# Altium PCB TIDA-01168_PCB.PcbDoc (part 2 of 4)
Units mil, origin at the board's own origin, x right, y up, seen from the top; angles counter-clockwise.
Board outline 7874.02 x 8344.02 mil, 4 copper layers (Top Layer, Signal Layer 1, Signal Layer 2, Bottom Layer), stack 65.748 mil thick; 480 components, 223 nets, 1266 pads, 1791 vias.
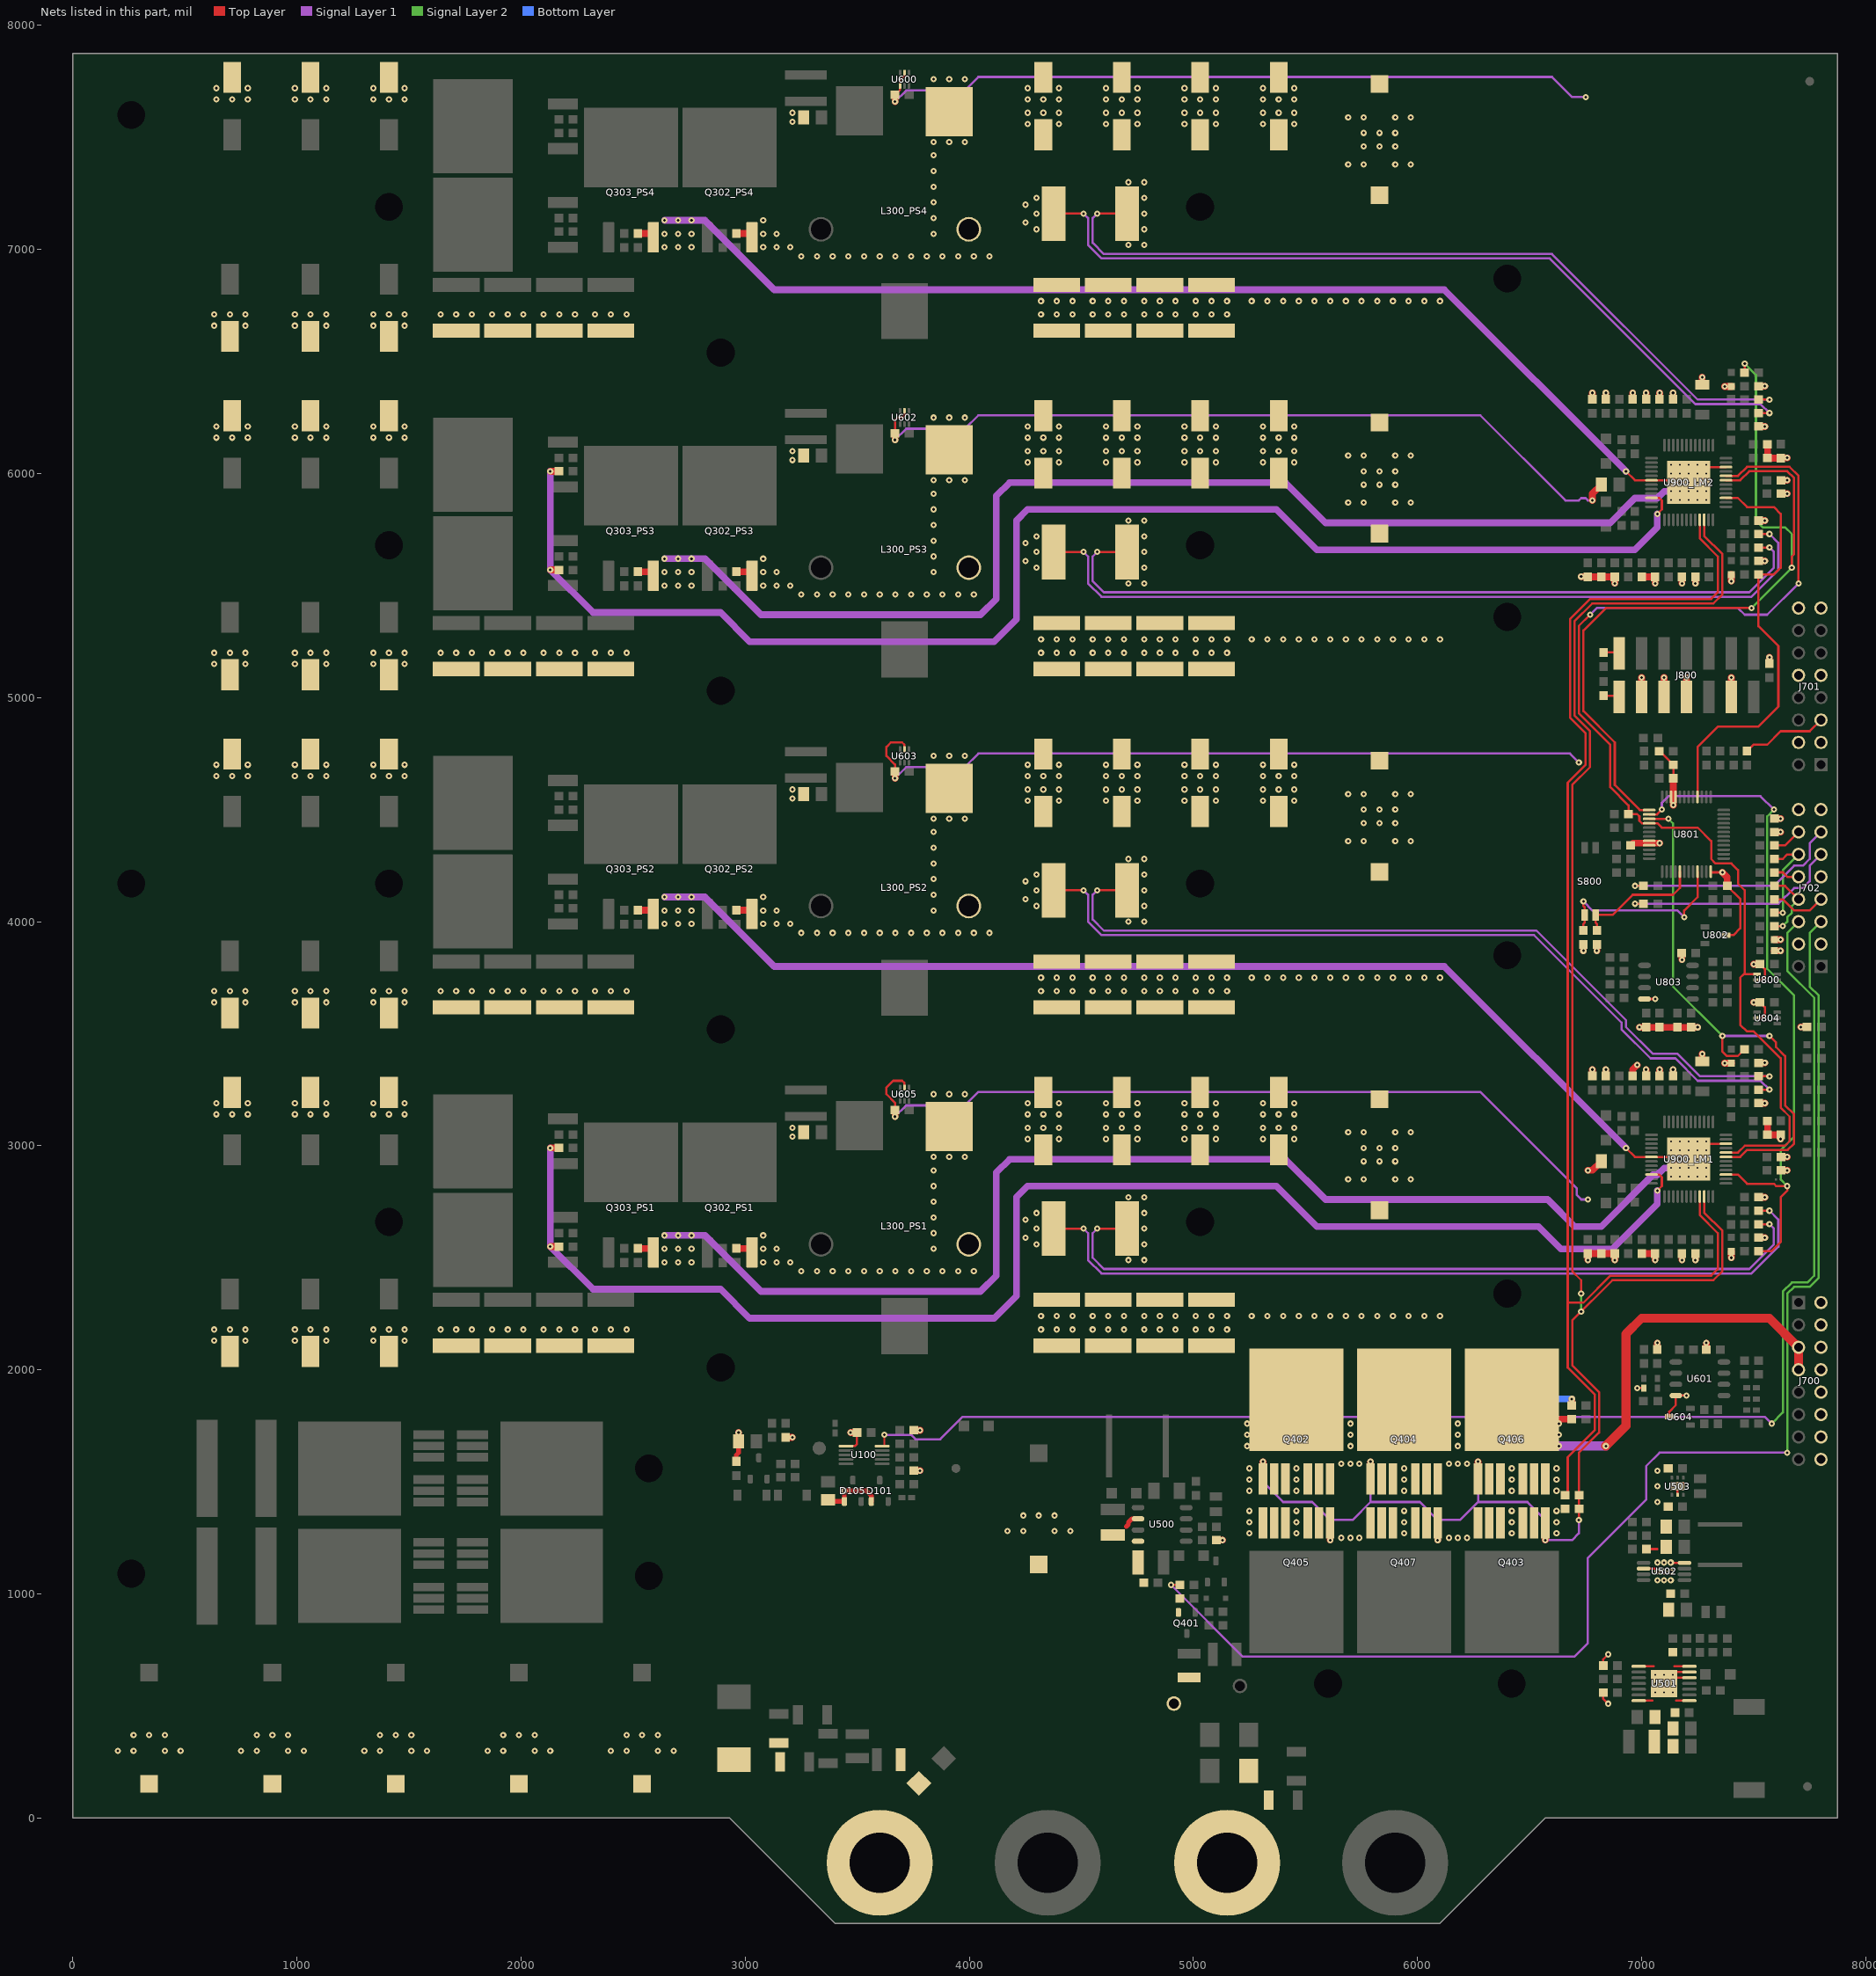
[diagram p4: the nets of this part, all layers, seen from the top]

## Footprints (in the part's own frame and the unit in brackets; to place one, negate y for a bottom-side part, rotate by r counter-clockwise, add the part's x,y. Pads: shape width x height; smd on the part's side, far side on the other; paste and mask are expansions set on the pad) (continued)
DRL0006A [mm] "SOTFL, 6-Flat Leads, Body 1.2x1.6x0.6mm, Pitch 0.5mm, TI recommended"
  rrect33% 0.67x0.3 smd: 1(-0.74,0.5) 2(-0.74,0) 3(-0.74,-0.5) 4(0.74,-0.5) 5(0.74,0) 6(0.74,0.5)
  silkscreen extent -0.9,-0.95 0.5,0.95, body extent -0.8,-0.8 0.8,0.8, height 0.61
DRV0006A [mm] "SON, 6-Leads, Body 2x2mm, Pitch 0.65mm, Thermal Pad 1.6x1mm, TI Recommended"
  rrect33% 0.45x0.3 smd: 1(-0.975,0.65) 2(-0.975,0) 3(-0.975,-0.65) 4(0.975,-0.65) 5(0.975,0) 6(0.975,0.65)
  rrect14% 1x0.7 on Top Paste: 7(0,0.45) 7(0,-0.45)
  rrect10% 1x1.6 smd paste-0.5: 7(0,0)
  silkscreen extent -1.05,-1.2 1.05,1.2, body extent -1.05,-1.05 1.05,1.05, height 0.81
FCC_disclaimer [mil]
Fiducial10-20 [mm]
  round 1 smd mask+0.5: 1(0,0)
  Top Layer keep-out circle w1.178: c0,0 r0.5
IHTH1125KZEB4R7 [mm] "TH, 2-Leads, Dia 28.575mm, Pin Spacing 16.764mm"
  round 2.8 hole 2.3: 1(-7.302,0) 2(9.461,0)
  silkscreen extent -14.35,-14.35 14.35,14.35, body extent -14.29,-14.29 14.29,14.29, height 10.74
Keystone_6095 [mm] "Banana Jack Uninsulated Standard Type"
  round 12 hole 6.858: 1(0,0)
  body extent -4.77,-5.5 4.75,5.49, height 2.39
Littelfuse_V20P17AUTO [mm] "TH, 2-Leads, Dia 20mm"
  round 1.65 hole 1.15: 1(-3.75,-1) 2(3.75,1)
  silkscreen extent -11.5,-2.5 11.5,2.5, body extent -11.5,-2.5 11.5,2.5, height 26.5
MSS1048 [mm] "Coilcraft recommended land pattern Document 462-2 Revised 06/09/09"
  rect 1.78x3.56 smd: 1(-4.7,0) 2(4.7,0)
  silkscreen extent -5.72,-5.59 5.72,5.59, body extent -5.15,-5.1 5.15,5.1, height 5.12
MSS5121 [mil] "Coilcraft recommended land pattern.  Document 495-2, rev 2/13/09"
  rect 20x200 smd: 1(-90,0) 2(90,0)
  Top Layer region: -31,-100 -31,-73.21 -31,-73.21 -60.67,-51.38 -77.31,-18.52 -77.36,18.32 -60.8,51.22 -31.19,73.13 -31.19,73.13 -31,73.4 -31,100 -100,100 -100,-100
  Top Layer region: 31,-100 31,-73.21 31,-73.21 60.67,-51.38 77.31,-18.52 77.36,18.32 60.8,51.22 31.19,73.13 31.19,73.13 31,73.4 31,100 100,100 100,-100
  silkscreen extent -120,-120 120,120, body extent -106,-106 106,106, height 87
MSS7341 [mm] "Coilcraft recommended land pattern Document 383-2 1/3/11"
  rect 0.7x7.1 smd: 1(-3.2,0) 2(3.2,0)
  Top Layer region: 1.05,3.55 3.55,3.55 3.55,-3.55 1.05,-3.55 1.05,-2.623 2.135,-1.85 2.745,-0.666 2.745,0.666 2.135,1.85 1.05,2.623 1.05,2.623
  Top Layer region: -1.05,3.55 -3.55,3.55 -3.55,-3.55 -1.05,-3.55 -1.05,-2.623 -2.135,-1.85 -2.745,-0.666 -2.745,0.666 -2.135,1.85 -1.05,2.623 -1.05,2.623
  silkscreen extent -3.8,-3.8 3.8,3.8, body extent -3.78,-3.78 3.78,3.78, height 4.12
MUB10A_N [mm] "TSSOP, 10-Leads, Body 3x3mm, Pitch 0.5mm, IPC Medium Density"
  oval 1.7x0.3 smd: 1(-2.05,1) 2(-2.05,0.5) 3(-2.05,0) 4(-2.05,-0.5) 5(-2.05,-1) 6(2.05,-1) 7(2.05,-0.5) 8(2.05,0) 9(2.05,0.5) 10(2.05,1)
  silkscreen extent -2.17,-1.6 0.8,1.82, body extent -1.6,-1.6 1.6,1.6, height 1.09
MXA14A_N [mm] "TSOP, 14-Leads, Body 5x4.4mm, Pitch 0.65mm, Exposed Pad, IPC Medium Density"
  oval 1.65x0.35 smd: 1(-2.875,1.95) 2(-2.875,1.3) 3(-2.875,0.65) 4(-2.875,0) 5(-2.875,-0.65) 6(-2.875,-1.3) 7(-2.875,-1.95) 8(2.875,-1.95) 9(2.875,-1.3) 10(2.875,-0.65) 11(2.875,0) 12(2.875,0.65) 13(2.875,1.3) 14(2.875,1.95)
  rect 3x3.1 smd: 15(0,0)
  silkscreen extent -3,-2.55 1.6,2.8, body extent -2.25,-2.55 2.25,2.55, height 1.1
Net-Tie_10mil [mil] "10mil net tie, no solder mask opening, no solder paste"
  rect 10x10 smd paste-5 mask-5: 1(-10,0) 2(10,0)
  Top Layer region: -6,5 6,5 6,-5 -6,-5
NPTH125mil [mil]
  round 120 hole 125 unplated mask+15: 1(0,0)
Pb-Free_Overlay_Small [mil]
PCV_800x1200 [mm] "SMD, 2-Leads, Dia 8mm"
  rect 3.5x2 smd: 1(-3.25,0) 2(3.25,0)
  silkscreen extent -4.25,-4.25 4.25,4.25, body extent -4.25,-4.25 4.25,4.25, height 12.01
PHP0048D_N [mm] "Thin QFP, 48-Leads, Body 7x7mm, Pitch 0.5mm, Thermal Pad 4.5x4.5mm, IPC Medium Density"
  rrect100% 1.45x0.3 smd: 1(-4.225,2.75) 2(-4.225,2.25) 3(-4.225,1.75) 4(-4.225,1.25) 5(-4.225,0.75) 6(-4.225,0.25) 7(-4.225,-0.25) 8(-4.225,-0.75) 9(-4.225,-1.25) 10(-4.225,-1.75) 11(-4.225,-2.25) 12(-4.225,-2.75) 25(4.225,-2.75) 26(4.225,-2.25) 27(4.225,-1.75) 28(4.225,-1.25) 29(4.225,-0.75) 30(4.225,-0.25) 31(4.225,0.25) 32(4.225,0.75) 33(4.225,1.25) 34(4.225,1.75) 35(4.225,2.25) 36(4.225,2.75)
  rrect100% 0.3x1.45 smd: 13(-2.75,-4.225) 14(-2.25,-4.225) 15(-1.75,-4.225) 16(-1.25,-4.225) 17(-0.75,-4.225) 18(-0.25,-4.225) 19(0.25,-4.225) 20(0.75,-4.225) 21(1.25,-4.225) 22(1.75,-4.225) 23(2.25,-4.225) 24(2.75,-4.225) 37(2.75,4.225) 38(2.25,4.225) 39(1.75,4.225) 40(1.25,4.225) 41(0.75,4.225) 42(0.25,4.225) 43(-0.25,4.225) 44(-0.75,4.225) 45(-1.25,4.225) 46(-1.75,4.225) 47(-2.25,4.225) 48(-2.75,4.225)
  rrect2% 4.9x4.9 smd: 49(0,0)
  silkscreen extent -4.17,3.33 -3.93,3.58, body extent -4.51,-4.51 4.51,4.51, height 1.2
PT0048A_N [mm] "Thin QFP, 48-Leads, Body 7x7mm, Pitch 0.5mm, IPC Medium Density"
  oval 1.45x0.3 smd: 1(-4.225,2.75) 2(-4.225,2.25) 3(-4.225,1.75) 4(-4.225,1.25) 5(-4.225,0.75) 6(-4.225,0.25) 7(-4.225,-0.25) 8(-4.225,-0.75) 9(-4.225,-1.25) 10(-4.225,-1.75) 11(-4.225,-2.25) 12(-4.225,-2.75) 25(4.225,-2.75) 26(4.225,-2.25) 27(4.225,-1.75) 28(4.225,-1.25) 29(4.225,-0.75) 30(4.225,-0.25) 31(4.225,0.25) 32(4.225,0.75) 33(4.225,1.25) 34(4.225,1.75) 35(4.225,2.25) 36(4.225,2.75)
  oval 0.3x1.45 smd: 13(-2.75,-4.225) 14(-2.25,-4.225) 15(-1.75,-4.225) 16(-1.25,-4.225) 17(-0.75,-4.225) 18(-0.25,-4.225) 19(0.25,-4.225) 20(0.75,-4.225) 21(1.25,-4.225) 22(1.75,-4.225) 23(2.25,-4.225) 24(2.75,-4.225) 37(2.75,4.225) 38(2.25,4.225) 39(1.75,4.225) 40(1.25,4.225) 41(0.75,4.225) 42(0.25,4.225) 43(-0.25,4.225) 44(-0.75,4.225) 45(-1.25,4.225) 46(-1.75,4.225) 47(-2.25,4.225) 48(-2.75,4.225)
  silkscreen extent -4.35,-3.1 3.1,3.57, body extent -4.51,-4.51 4.51,4.51, height 1.5
Samtec_TSM-107-01-x-DV [mm] "Header, 2.54mm, 7x2, SMT"
  rect 3.68x1.27 smd: 1(-2.475,7.62) 2(2.475,7.62) 3(-2.475,5.08) 4(2.475,5.08) 5(-2.475,2.54) 6(2.475,2.54) 7(-2.475,0) 8(2.475,0) 9(-2.475,-2.54) 10(2.475,-2.54) 11(-2.475,-5.08) 12(2.475,-5.08) 13(-2.475,-7.62) 14(2.475,-7.62)
  silkscreen extent -1.65,-8.89 1.65,9.03, body extent -3.85,-8.89 3.85,8.89, height 9.65
SER2915L [mm] "COILCRAFT"
  rect 5.59x5.33 smd: 1(-14.355,5.075) 2(-14.455,-5.075)
  rect 6.35x5.28 smd: 3(8.25,0)
  silkscreen extent -11.04,-14 10.81,13.9, body extent -16.7,-14.05 11.22,13.85, height 15.4
SMA [mm] "Molded Diode, 2-Leads, Body 4.3x2.6mm, IPC Medium Density, based on OnSemi component dimensions and land pattern"
  rect 2x2 smd: 1(-2,0) 2(2,0)
  silkscreen extent -3.66,-1.57 2.79,1.57, body extent -2.6,-1.3 2.6,1.3, height 2.42
SMB [mil] "Molded Diode, 2-Leads, Body 5.4x3.6mm, IPC Medium Density, based on OnSemi component dimensions"
  rect 85x107.99 smd: 1(-87.01,0) 2(87.01,0)
  silkscreen extent -155,-82 125,82, body extent -106,-71 106,71, height 91
SMC [mil] "Molded Diode, 2-Leads, Body 6.9x5.8mm, IPC Medium Density, based on OnSemi component dimensions and land patterns"
  rect 110x150 smd: 1(-140.49,0) 2(140.49,0)
  silkscreen extent -221,-124 189,123, body extent -156,-116 156,116, height 91
SOD-123 [mm] "On Semi recommended land pattern"
  rect 0.915x1.22 smd: 1(-1.637,0) 2(1.637,0)
  silkscreen extent -2.74,-1.17 2.03,1.17, body extent -1.93,-0.9 1.93,0.9, height 1.35
SOD-123F [mm] "NXP recommended land pattern"
  rect 1.2x1.2 smd paste-0.05: 1(-1.4,0) 2(1.4,0)
  silkscreen extent -2.64,-1.12 2.01,1.12, body extent -1.8,-0.85 1.8,0.85, height 1.2
SOD-323 [mm] "NXP recommended land pattern"
  rect 0.6x0.6 smd paste-0.05: 1(-1.1,0) 2(1.1,0)
  silkscreen extent -2.06,-0.86 1.53,0.86, body extent -1.3,-0.67 1.3,0.68, height 1.1
SOD-523 [mm] "NXP Semiconductor recommended land pattern, nominal STEP model"
  rect 0.8x0.6 smd paste-0.05: 1(-0.55,0) 2(0.55,0)
  silkscreen extent -1.65,-0.66 1.2,0.66, body extent -0.8,-0.4 0.8,0.4, height 0.72
SOT-23 [mm] "SOT23, 3-Leads, Body 2.9x1.3mm, Pitch 0.95mm, Lead Span 2.5mm, IPC Medium Density"
  rrect50% 1x0.6 smd: 1(-1.2,0.95) 2(-1.2,-0.95) 3(1.2,0)
  silkscreen extent -1.62,-1.5 0.7,1.5, body extent -1.16,-1.45 1.21,1.45, height 1
Sullins_xxxC008DAAN [mm] "Header, 2.54mm, 8x2, TH"
  rect 1.5x1.5 hole 1: 1(-1.27,8.89)
  round 1.5 hole 1: 2(1.27,8.89) 3(-1.27,6.35) 4(1.27,6.35) 5(-1.27,3.81) 6(1.27,3.81) 7(-1.27,1.27) 8(1.27,1.27) 9(-1.27,-1.27) 10(1.27,-1.27) 11(-1.27,-3.81) 12(1.27,-3.81) 13(-1.27,-6.35) 14(1.27,-6.35) 15(-1.27,-8.89) 16(1.27,-8.89)
  silkscreen extent -2.5,-10.16 2.5,10.6, body extent -2.5,-10.16 2.5,10.16, height 8.34
SW_218-2LP [mm] "SMD, 4-Leads, Body 3.71x5.8mm, Pitch 1.27mm"
  rect 1.27x0.76 smd: 1(-3.81,0.635) 2(-3.81,-0.635) 3(3.81,-0.635) 4(3.81,0.635)
  silkscreen extent -2.9,-1.86 2.9,2.09, body extent -4.22,-1.86 4.22,1.85, height 2.62
TP_60MIL-SMT [mil]
  round 60 smd paste-30: 1(0,0)
  silkscreen extent -40,-41 40,40
UCZ_1250x1350 [mm] "SMD, 2-Leads, Dia 12.5mm"
  rect 2x2 smd: 1(-6.3,0) 2(6.3,0)
  Top Layer region: 8.8,-3.5 8.8,3.5 3.8,3.5 3.8,1 1.5,1 1.5,-1 3.8,-1 3.8,-3.5
  Top Layer region: -8.8,-3.5 -8.8,3.5 -3.8,3.5 -3.8,1 -1.5,1 -1.5,-1 -3.8,-1 -3.8,-3.5
  silkscreen extent -6.9,-6.9 6.9,6.9, body extent -6.9,-6.9 6.9,6.9, height 14.51
WL-SMCW_GREEN [mm] "WURTH"
  rect 0.8x0.8 smd: 1(-0.8,0) 2(0.8,0)
  silkscreen extent -1.9,-0.8 1.2,0.8, body extent -0.85,-0.45 0.85,0.45, height 0.8
WL-SMCW_RED [mm] "WURTH"
  rect 0.8x0.8 smd: 1(-0.8,0) 2(0.8,0)
  silkscreen extent -1.9,-0.8 1.2,0.8, body extent -0.85,-0.45 0.85,0.45, height 0.8
WL-SMCW_YELLOW [mm] "WURTH"
  rect 0.8x0.8 smd: 1(-0.8,0) 2(0.8,0)
  silkscreen extent -1.9,-0.8 1.2,0.8, body extent -0.85,-0.45 0.85,0.45, height 0.8
XAL1060 [mm] "COILCRAFT"
  rect 2.39x11 smd: 1(-3.325,0) 2(3.325,0)
  silkscreen extent -5.3,-6 5.3,6, body extent -5.25,-5.9 5.25,5.9, height 6

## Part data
C100 C103 C401 C403: "CAP, CERM, 0.47 µF, 100 V, +/- 10%, X7R, AEC-Q200 Grade 1, 1210"
C101 C102 C104 C105 C400 C402: "CAP, CERM, 10 µF, 50 V, +/- 10%, X7S, AEC-Q200 Grade 1, 1210"
C106 C107 C507: "CAP, CERM, 0.01 µF, 100 V, +/- 10%, X7R, 0805"
C108 C505 C903_LM1 C903_LM2 C915_LM1 C915_LM2: "CAP, CERM, 0.047 µF, 25 V, +/- 10%, X7R, AEC-Q200 Grade 1, 0603"
C200 C201 C202 C203 C204: "CAP, AL, 150 µF, 80 V, +/- 20%, 0.2 ohm, AEC-Q200 Grade 1, SMD"
C300_PS1 C300_PS2 C300_PS3 C300_PS4 C311_PS1 C311_PS2 C311_PS3 C311_PS4 C312_PS1 C312_PS2 C312_PS3 C312_PS4 C313_PS1 C313_PS2 C313_PS3 C313_PS4 C314_PS1 C314_PS2 C314_PS3 C314_PS4 C315_PS1 C315_PS2 C315_PS3 C315_PS4 C316_PS1 C316_PS2 C316_PS3 C316_PS4 C317_PS1 C317_PS2 C317_PS3 C317_PS4 C318_PS1 C318_PS2 C318_PS3 C318_PS4 C319_PS1 C319_PS2 C319_PS3 C319_PS4: "CAP, Aluminum Polymer, 39 µF, 63 V, +/- 20%, 0.029 ohm, AEC-Q200 Grade 2, D8xL12mm SMD"
C301_PS1 C301_PS2 C301_PS3 C301_PS4 C302_PS1 C302_PS2 C302_PS3 C302_PS4 C303_PS1 C303_PS2 C303_PS3 C303_PS4 C304_PS1 C304_PS2 C304_PS3 C304_PS4 C305_PS1 C305_PS2 C305_PS3 C305_PS4 C306_PS1 C306_PS2 C306_PS3 C306_PS4 C307_PS1 C307_PS2 C307_PS3 C307_PS4 C308_PS1 C308_PS2 C308_PS3 C308_PS4: "CAP, CERM, 4.7 µF, 100 V, +/- 20%, X7R, AEC-Q200 Grade 1,"
C309_PS1 C309_PS2 C309_PS3 C309_PS4 C501: "CAP, AL, 180 µF, 63 V, +/- 20%, 0.2 ohm, AEC-Q200 Grade 1, SMD"
C310_PS1 C310_PS2 C310_PS3 C310_PS4: "CAP, CERM, 100 pF, 100 V, +/- 5%, C0G/NP0, AEC-Q200 Grade 1, 0805"
C404: "CAP, CERM, 68 pF, 50 V, +/- 5%, C0G/NP0, AEC-Q200 Grade 1, 0603"
C500 C502 C506: "CAP, CERM, 4.7 µF, 100 V, +/- 10%, X7S, AEC-Q200 Grade 1, 1210"
C503: "CAP, CERM, 390 pF, 50 V, +/- 5%, C0G/NP0, 0603"
C504 C510 C519 C520 C801 C802 C909_LM1 C909_LM2: "CAP, CERM, 1 µF, 25 V, +/- 10%, X7R, AEC-Q200 Grade 1, 0603"
C508 C912_LM1 C912_LM2: "CAP, CERM, 3300 pF, 100 V, +/- 10%, X7R, AEC-Q200 Grade 1, 0603"
C509 C600 C601 C602 C603 C800 C913_LM1 C913_LM2: "CAP, CERM, 0.01 µF, 50 V, +/- 10%, X7R, AEC-Q200 Grade 1, 0603"
C511 C910_LM1 C910_LM2: "CAP, CERM, 4.7 µF, 16 V, +/- 10%, X7R, AEC-Q200 Grade 1, 0805"
C512 C515 C517 C518: "CAP, CERM, 10 µF, 16 V, +/- 10%, X7S, AEC-Q200 Grade 1, 0805"
C513 C516 C604 C805 C807 C811 C812: "CAP, CERM, 0.1 µF, 50 V, +/- 10%, X7R, 0603"
C514: "CAP, CERM, 15 pF, 50 V, +/- 5%, C0G/NP0, AEC-Q200 Grade 1, 0603"
C803 C804: "CAP, CERM, 2.2 µF, 6.3 V, +/- 10%, X7R, AEC-Q200 Grade 1, 0603"
C806 C808 C809 C810: "CAP, CERM, 330 pF, 100 V, +/- 5%, C0G/NP0, 0603"
C900_LM1 C900_LM2 C905_LM1 C905_LM2 C906_LM1 C906_LM2 C920_LM1 C920_LM2: "CAP, CERM, 1000 pF, 100 V, +/- 5%, C0G/NP0, AEC-Q200 Grade 1, 0603"
C901_LM1 C901_LM2 C917_LM1 C917_LM2: "CAP, CERM, 0.15 µF, 25 V, +/- 10%, X7R, 0603"
C902_LM1 C902_LM2 C904_LM1 C904_LM2 C914_LM1 C914_LM2 C916_LM1 C916_LM2 C918_LM1 C918_LM2 C919_LM1 C919_LM2: "CAP, CERM, 100 pF, 100 V, +/- 5%, C0G/NP0, AEC-Q200 Grade 1, 0603"
C907_LM1 C907_LM2: "CAP, CERM, 1 µF, 100 V, +/- 10%, X7R, 1206"
C908_LM1 C908_LM2 C911_LM1 C911_LM2: "CAP, CERM, 0.47 µF, 25 V, +/- 10%, X7R, AEC-Q200 Grade 1, 0603"
D100 D102: "Diode, Ultrafast, 100 V, 0.15 A, SOD-123"
D101 D105: "Diode, Zener, 68 V, 225 mW, SOT-23"
D103: "Diode, TVS, Bi, 78 V, SMA"
D104: "Diode, TVS, Uni, 78 V, 126 Vc, SMC"
D106 D107: "Diode, Switching, 100 V, 0.25 A, SOD-523"
D400 D500 D501 D502 D900_LM1 D900_LM2 D901_LM1 D901_LM2: "Diode, Schottky, 60 V, 1 A, SOD-123F"
D401: "Diode, Zener, 15 V, 300 mW, SOD-323"
D402: "Diode, TVS, Uni, 28 V, 600 W, SMB"
D403: "Diode, TVS, Uni, 24 V, 600 W, SMB"
D600 D601 D602 D603 D604: "Diode, Schottky, 70 V, 0.07 A, SOD-523"
D700 D701 D800: "LED, Green, SMD"
D801 D902_LM1 D902_LM2 D903_LM1 D903_LM2: "LED, Yellow, SMD"
D802 D803 D804: "LED, Super Red, SMD"
FID1 FID2 FID3: "Fiducial mark.  There is nothing to buy or mount."
J1 J2 J3 J4: "Standard Banana Jack, Uninsulated"
J700 J701 J702: "Header, 2.54mm, 8x2, Gold, TH"
J800: "Header, 2.54mm, 7x2, Gold, SMT"
L200 L201: "Inductor, Shielded, Composite, 400 nH, 36.8 A, 0.0008 ohm, AEC-Q200 Grade 1, SMD"
L300_PS1 L300_PS2 L300_PS3 L300_PS4: "Inductor, Shielded, 4.7 µH, 50 A, 0.00143 ohm, AEC-Q200 Grade 0, TH"
L300_PS1 L300_PS2 L300_PS3 L300_PS4: "Inductor, Shielded E Core, Ferrite, 4.7 µH, 30 A, 0.0015 ohm, SMD"
L500: "Inductor, Shielded Drum Core, Ferrite, 220 µH, 0.51 A, 0.65 ohm, AEC-Q200 Grade 1, SMD"
L501: "Inductor, Shielded Drum Core, Ferrite, 180 µH, 1.02 A, 0.45 ohm, SMD"
L502: "Inductor, Shielded Drum Core, Ferrite, 33 µH, 0.67 A, 0.48 ohm, SMD"
L800: "Ferrite Bead, 120 ohm @ 100 MHz, 0.5 A, 0603"
Logo2: library part Pb-Free
Logo3: library part FCC_disclaimer, "FCC_disclaimer"
MH1 MH2 MH3 MH4 MH6 MH7 MH8 MH9 MH10 MH11 MH12 MH13 MH14 MH16 MH17 MH18 MH19 MH20 MH21 MH25 MH26 MH27 MH28: library part "Mounting Hole (non-standard) No Pad", "PCB Mounting Hole, No Pad"
NT1: "Single point connection between nets."
Q100 Q101 Q102 Q103: "MOSFET, N-CH, 100 V, 180 A, AEC-Q101, DDPAK-7"
Q104: library part "MMBTA06-7-F, Diodes Inc.", "Transistor, NPN, 80 V, 0.5 A, SOT-23"
Q300_PS1 Q300_PS2 Q300_PS3 Q300_PS4 Q301_PS1 Q301_PS2 Q301_PS3 Q301_PS4 Q302_PS1 Q302_PS2 Q302_PS3 Q302_PS4 Q303_PS1 Q303_PS2 Q303_PS3 Q303_PS4: "MOSFET, N-CH, 100 V, 65 A, DDPAK"
Q400: "MOSFET, P-CH, -40 V, -2.3 A, SOT-23"
Q401: library part "BC846B,215, NXP Semiconductor", "Transistor, NPN, 65 V, 0.1 A, SOT-23"
Q402 Q403 Q404 Q405 Q406 Q407: "MOSFET, N-CH, 40 V, 240 A, AEC-Q101, DDPAK-7"
R100 R108 R400 R508 R606: "RES, 100 k, 1%, 0.1 W, 0603"
R101: "RES, 1.00 k, 1%, 0.1 W, 0603"
R103: "RES, 2.87 k, 1%, 0.1 W, 0603"
R104: "RES, 20.5 k, 1%, 0.1 W, 0603"
R105: "RES, 2.00 k, 1%, 0.1 W, 0603"
R106: "RES, 330 k, 1%, 0.1 W, 0603"
R107: "RES, 2.70 k, 1%, 0.1 W, 0603"
R109 R110 R405 R406 R603: "RES, 0, 5%, 0.1 W, 0603"
R300_PS1 R300_PS2 R300_PS3 R300_PS4: "RES, 0.001, 1%, 4 W, AEC-Q200 Grade 0, 10x5.2mm"
R301_PS1 R301_PS2 R301_PS3 R301_PS4 R304_PS1 R304_PS2 R304_PS3 R304_PS4 R308_PS1 R308_PS2 R308_PS3 R308_PS4 R309_PS1 R309_PS2 R309_PS3 R309_PS4: "RES, 51.0 k, 1%, 0.1 W, 0603"
R302_PS1 R302_PS2 R302_PS3 R302_PS4 R305_PS1 R305_PS2 R305_PS3 R305_PS4 R306_PS1 R306_PS2 R306_PS3 R306_PS4 R307_PS1 R307_PS2 R307_PS3 R307_PS4: "RES, 1.00, 1%, 0.1 W, 0603"
R303_PS1 R303_PS2 R303_PS3 R303_PS4: "RES, 10.0, 1%, 1 W, 1218"
R401 R402 R403 R507 R511 R600 R601 R608 R808 R809 R817 R818 R835 R836 R905_LM1 R905_LM2 R906_LM1 R906_LM2 R908_LM1 R908_LM2 R911_LM1 R911_LM2: "RES, 10.0 k, 1%, 0.1 W, 0603"
R404: "RES, 220 k, 1%, 0.1 W, 0603"
R500: "RES, 0.5, 1%, 0.5 W, 1206"
R501 R506 R510: "RES, 0, 1%, 0.5 W, 0805"
R502: "RES, 180, 5%, 0.1 W, 0603"
R503: "RES, 47.0 k, 1%, 0.1 W, 0603"
R504: "RES, 2.20 k, 1%, 0.1 W, 0603"
R505: "RES, 169 k, 1%, 0.1 W, 0603"
R509: "RES, 3.32 k, 1%, 0.1 W, 0603"
R512: "RES, 3.16 k, 1%, 0.1 W, 0603"
R602: "RES, 8.20 k, 1%, 0.1 W, 0603"
R604: "RES, 7.50 k, 1%, 0.1 W, 0603"
R605 R700 R701 R801 R807: "RES, 680, 1%, 0.1 W, 0603"
R607: "RES, 102 k, 1%, 0.1 W, 0603"
R800 R803 R805: "RES, 4.70 k, 1%, 0.1 W, 0603"
R802 R806 R833 R834 R916_LM1 R916_LM2 R917_LM1 R917_LM2: "RES, 1.50 k, 1%, 0.1 W, 0603"
R804: "RES, 2.55 k, 1%, 0.1 W, 0603"
R810 R811 R814 R815 R816 R820 R821 R823 R824 R825 R826 R827 R828: "RES, 22.0, 1%, 0.1 W, 0603"
R812 R819: "RES, 30.1 k, 0.5%, 0.1 W, 0603"
R813 R822 R830 R832: "RES, 1.00 k, 0.5%, 0.1 W, 0603"
R829 R831: "RES, 10.0 k, 0.5%, 0.1 W, 0603"
R900_LM1 R900_LM2 R920_LM1 R920_LM2: "RES, 634, 1%, 0.1 W, 0603"
R901_LM1 R901_LM2 R904_LM1 R904_LM2 R914_LM1 R914_LM2 R915_LM1 R915_LM2: "RES, 10.0, 1%, 0.1 W, 0603"
R902_LM1 R902_LM2 R903_LM1 R903_LM2: "RES, 95.3 k, 1%, 0.1 W, 0603"
R907_LM1 R907_LM2 R913_LM1 R913_LM2: "RES, 2.00, 1%, 0.1 W, 0603"
R909_LM1 R909_LM2 R912_LM1 R912_LM2: "RES, 40.2 k, 1%, 0.1 W, 0603"
R910_LM1 R910_LM2: "RES, 24.0, 1%, 0.1 W, 0603"
R918_LM1 R918_LM2 R919_LM1 R919_LM2: "RES, 64.9 k, 1%, 0.1 W, 0603"
RV400: "VARISTOR 27V, TH"
S800: "Switch, SPST, 2 Pos, 25mA, 24VDC, SMD"
TP100: "TEST POINT.  No entry in BOM."
U100: "High-Side Protection Controller with Low Quiescent Current, 10-pin MSOP, Pb-Free"
U500: "1.5-A PEAK BOOST / BUCK / INVERTING SWITCHING REGULATOR, D0008A"
U501: "High Voltage 1A Step Down Switching Regulator, 14-pin TSSOP-EP, Pb-Free"
U502: "4.5V to 18V Input, 500mA Synchronous Step Down SWIFT Converter with Advanced Eco-mode, DGK0008A"
U503: "Ultra Low-Noise, 500-mA Linear Regulator for RF and Analog Circuits - Requires No Bypass Capacitor, DRV0006A"
U600 U602 U603 U605: "Low-Power Digital Temperature Sensor With SMBus and Two-Wire Serial Interface in SOT563, DRL0006A"
U601: "Dual Processor Supervisory Circuits with power Fail, D0008A"
U604 U802: "Automotive Catalog Adjustable Precision Shunt Regulator, 34 ppm / degC, 100 mA, -40 to 125 degC, 3-pin SOT-23 (DBZ), Green (RoHS & no Sb/Br)"
U800 U804: "Dual Schmitt Trigger Buffer, DCK0006A (SOT-6)"
U801: "Piccolo Microcontroller, PT0048A (LQFP-48)"
U803: library part TLC2272AQDRQ1, "Automotive Catalog Advanced LinCMOS(TM) Rail-to-Rail Operational Amplifier, 4.4 to 16 V, -40 to 125 degC, 8-pin SOIC (D0008A), Green (RoHS & no Sb/Br)"
U900_LM1 U900_LM2: "Dual Channel 48V-12V Bidirectional Current Controller, PHP0048D"
ZZ1: library part AssemblyNoteLabel
ZZ2 ZZ3 ZZ4: library part AssemblyNote

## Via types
v1: diameter 28, hole 12, Top Layer to Bottom Layer, 1729 vias
v2: diameter 19.68, hole 7.87, Top Layer to Bottom Layer, 52 vias
v3: diameter 15.75, hole 7.87, Top Layer to Bottom Layer, 9 vias
v4: diameter 29, hole 12, Top Layer to Bottom Layer, 1 vias

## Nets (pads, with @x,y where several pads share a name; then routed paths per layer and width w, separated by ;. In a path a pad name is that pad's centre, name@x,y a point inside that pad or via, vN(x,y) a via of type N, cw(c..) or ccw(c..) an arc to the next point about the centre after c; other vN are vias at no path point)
ADCINA6: J702.13 R821.2 | length 1008.9
  Top Layer w10: v1(6970,4160) R821.2@7008.5,4160
  Signal Layer 1 w10: v1(6970,4160) 7590,4160 7680,4250 7720,4250 7750,4280 7750,4350 J702.13@7800,4400
ADCINA7: J702.11 R823.2 | length 1000.6
  Top Layer w10: v1(6970,4080) R823.2@7008.5,4080
  Signal Layer 1 w10: v1(6970,4080) 7610,4080 7680,4150 7720,4150 7750,4180 7750,4250 J702.11@7800,4300
ADCINB1: J702.7 R824.2 | length 249.9
  Top Layer w10: R824.2@7591.5,4100 7630,4100 7680,4050 7750,4050 J702.7@7800,4100
ADCINB2: J702.8 R700.1 R825.2 | length 322.4
  Top Layer w10: R700.1@7590,3980 R700.1@7591.5,3980 v1(7630,3980) ; R825.2@7591.5,4160 7640,4160 J702.8@7700,4100
  Signal Layer 2 w10: v1(7630,3980) 7650,4000 7650,4020 7670,4040 7670,4070 J702.8@7700,4100
ADCINB3: J702.10 R826.2 | length 116.8
  Top Layer w10: R826.2@7591.5,4220 7630,4220 7650,4200 J702.10@7700,4200
ADCINB4: J702.12 R701.1 R827.2 | length 445.8
  Top Layer w10: R701.1@7590,4040 R701.1@7591.5,4040 v1(7630,4040) ; R827.2@7591.5,4280 7630,4280 7650,4300 J702.12@7700,4300
  Signal Layer 2 w10: v1(7630,4040) 7630,4230 J702.12@7700,4300
ADCINB6: J702.14 R828.2 | length 133.4
  Top Layer w10: R828.2@7591.5,4340 7640,4340 J702.14@7700,4400
BRKG: C404.1 Q402.1 Q403.1 Q404.1 Q405.1 Q406.1 Q407.1 R404.1 U900_LM1.34 U900_LM2.34 | length 9208.4
  Top Layer w10: v1(6720,1330) 6720,1630 6810,1720 6810,1900 6690,2020 6690,2220 6870,2400 7320,2400 7360,2440 7360,2620 7278.9,2701.1 U900_LM1.34@7278.9,2773.66 ; v1(6730,2340) 6730,2400 6690,2440 6690,4610 6770,4690 6770,4850 6700,4920 6700,5340 6780,5420 7320,5420 7360,5460 7360,5640 7278.9,5721.1 U900_LM2.34@7278.9,5793.66
  Top Layer w30: Q402.1@5310,1513 v1(5310,1590) ; v1(5610,1240) Q405.1@5610,1317 ; Q404.1@5790,1513 v1(5790,1590) ; v1(6090,1240) Q407.1@6090,1317 ; Q406.1@6270,1513 v1(6270,1590) ; v1(6570,1240) Q403.1@6570,1317
  Signal Layer 1 w10: v1(5310,1590) 5310,1500 5400,1410 5530,1410 5610,1330 ; v1(5610,1240) 5610,1330 ; v1(5790,1590) 5790,1410 ; v1(6090,1240) 6090,1330 ; v1(6270,1590) 6270,1410 ; v1(6720,1330) 6720,1270 6690,1240 v1(6570,1240) 6570,1330 6490,1410 6270,1410 ; 5610,1330 5710,1330 5790,1410 ; 5790,1410 6010,1410 6090,1330 ; 6090,1330 6190,1330 6270,1410
  Signal Layer 2 w10: v1(6730,2260) v1(6730,2340)
BRKS: C404.2 Q402.2 Q402.3 Q402.5 Q402.6 Q402.7 Q403.2 Q403.3 Q403.5 Q403.6 Q403.7 Q404.2 Q404.3 Q404.5 Q404.6 Q404.7 Q405.2 Q405.3 Q405.5 Q405.6 Q405.7 Q406.2 Q406.3 Q406.5 Q406.6 Q406.7 Q407.2 Q407.3 Q407.5 Q407.6 Q407.7 R404.2 U900_LM1.33 U900_LM2.33 | length 6239.1
  Top Layer w10: C404.2@6658.5,1440 6670,1440 6670,1610 6790,1730 6790,1890 6670,2010 6670,2300 ; U900_LM1.33@7259.21,2773.66 7259.21,2690.79 7340,2610 7340,2450 7310,2420 6860,2420 6740,2300 6670,2300 ; U900_LM2.33@7259.21,5793.66 7259.21,5710.79 7340,5630 7340,5470 7310,5440 6770,5440 6680,5350 6680,4910 6750,4840 6750,4700 6670,4620 6670,2300
  other v1: 5660,1250 5700,1250 5740,1250 6140,1250 6180,1250 6220,1250 5250,1270 5460,1270 5940,1270 6420,1270 6620,1270 5250,1320 5460,1320 5940,1320 6420,1320 6620,1320 5250,1370 5460,1370 5940,1370 6420,1370 6620,1370 5250,1460 5460,1460 5940,1460 6420,1460 6620,1460 5250,1510 5460,1510 5940,1510 6420,1510 6620,1510 5250,1560 5460,1560 5940,1560 6420,1560 6620,1560 5660,1580 5700,1580 5740,1580 6140,1580 6180,1580 6220,1580
CFG0: R835.2 S800.3 U801.9 | length 839.8
  Top Layer w10: R835.2@6740,3961.5 6740,3990 6745,3995 S800.3@6745,4030 6745,4065 6740,4070 v1(6740,4090) ; v1(7190,4020) 7190,4050 7249.21,4109.21 U801.9@7249.21,4223.66
  Signal Layer 1 w10: v1(6740,4090) 6780,4050 7160,4050 v1(7190,4020)
CFG1: R836.2 S800.4 U801.5 | length 569.1
  Top Layer w10: R836.2@6800,3961.5 6800,3990 6795,3995 S800.4@6795,4030 6870,4030 6960,4120 7140,4120 7170.47,4150.47 U801.5@7170.47,4223.66
CLK: J701.5 R814.1 | length 387.4
  Top Layer w10: R814.1@7470,4761.5 7498.5,4790 7560,4790 7620,4850 7750,4850 J701.5@7800,4900
CS1A_A: L300_PS3.1 R300_PS3.1 R901_LM2.2 | length 3661.3
  Top Layer w10: R300_PS3.1@4376.61,5650 v1(4510,5650) ; R901_LM2.2@7521.5,5730 v1(7570,5730)
  Signal Layer 1 w10: v1(4510,5650) 4530,5630 4530,5510 4590,5450 7490,5450 7610,5570 7610,5690 v1(7570,5730)
  other v1: 3840,5560 4300,5580 4250,5610 3840,5630 4300,5650 4250,5690 3840,5700 4300,5720 3840,5770 3840,5840 3840,5910 3840,5970 3910,5970 3980,5970 3840,6250 3910,6250 3980,6250
CS1A_B: L300_PS1.1 R300_PS1.1 R901_LM1.2 | length 3661.3
  Top Layer w10: R300_PS1.1@4376.61,2630 v1(4510,2630) ; R901_LM1.2@7521.5,2710 v1(7570,2710)
  Signal Layer 1 w10: v1(4510,2630) 4530,2610 4530,2490 4590,2430 7490,2430 7610,2550 7610,2670 v1(7570,2710)
  other v1: 3840,2540 4300,2560 4250,2590 3840,2610 4300,2630 4250,2670 3840,2680 4300,2700 3840,2750 3840,2820 3840,2890 3840,2950 3910,2950 3980,2950 3840,3230 3910,3230 3980,3230
CS1B_A: C305_PS1.1 C305_PS2.1 C305_PS3.1 C305_PS4.1 C306_PS1.1 C306_PS2.1 C306_PS3.1 C306_PS4.1 C307_PS1.1 C307_PS2.1 C307_PS3.1 C307_PS4.1 C308_PS1.1 C308_PS2.1 C308_PS3.1 C308_PS4.1 C309_PS1.1 C309_PS2.1 C309_PS3.1 C309_PS4.1 C316_PS1.1 C316_PS2.1 C316_PS3.1 C316_PS4.1 C317_PS1.1 C317_PS2.1 C317_PS3.1 C317_PS4.1 C318_PS1.1 C318_PS2.1 C318_PS3.1 C318_PS4.1 C319_PS1.1 C319_PS2.1 C319_PS3.1 C319_PS4.1 J700.5 J700.7 Q402.4 Q404.4 Q406.4 R300_PS1.2 R300_PS2.2 R300_PS3.2 R300_PS4.2 R405.1 R904_LM1.2 R904_LM2.2 R914_LM1.2 R914_LM2.2 | length 16075.9
  Top Layer w10: v1(4570,2630) R300_PS1.2@4703.39,2630 ; v1(4570,4140) R300_PS2.2@4703.39,4140 ; v1(4570,5650) R300_PS3.2@4703.39,5650 ; v1(4570,7160) R300_PS4.2@4703.39,7160 ; R904_LM1.2@7521.5,2650 v1(7570,2650) ; R914_LM1.2@7521.5,3310 v1(7570,3310) ; R904_LM2.2@7521.5,5670 v1(7570,5670) ; R914_LM2.2@7521.5,6330 v1(7570,6330)
  Top Layer w30: 6640,1780 R405.1@6688.5,1780
  Top Layer w40: v1(6840,1660) 6930,1750 6930,2160 7000,2230 7570,2230 J700.5@7700,2100 J700.7@7700,2000
  Signal Layer 1 w10: v1(4570,2630) 4550,2610 4550,2500 4600,2450 7480,2450 7590,2560 7590,2630 v1(7570,2650) ; v1(4570,4140) 4550,4120 4550,4010 4600,3960 6530,3960 6930,3560 6930,3530 7050,3410 7160,3410 7260,3310 v1(7570,3310) ; v1(4570,5650) 4550,5630 4550,5520 4600,5470 7480,5470 7590,5580 7590,5650 v1(7570,5670) ; v1(4570,7160) 4550,7140 4550,7030 4600,6980 6600,6980 7250,6330 v1(7570,6330)
  Signal Layer 1 w40: v1(6630,1660) v1(6840,1660)
  other v1: 5240,1660 5700,1660 6180,1660 5240,1710 5700,1710 6180,1710 6630,1710 5240,1760 5700,1760 6180,1760 6630,1760 4320,2240 4390,2240 4460,2240 4550,2240 4620,2240 4690,2240 4780,2240 4850,2240 4920,2240 5010,2240 5080,2240 5150,2240 5260,2240 5330,2240 5400,2240 5470,2240 5540,2240 5610,2240 5680,2240 5750,2240 5820,2240 5890,2240 5960,2240 6030,2240 6100,2240 4710,2490 4780,2490 4780,2560 4780,2630 4780,2700 4710,2770 4780,2770 5690,2850 5760,2850 5900,2850 5970,2850 5760,2930 5830,2930 5900,2930 4260,3030 4400,3030 4610,3030 4750,3030 4960,3030 5100,3030 5310,3030 5450,3030 4260,3080 4330,3080 4400,3080 4610,3080 4680,3080 4750,3080 4960,3080 5030,3080 5100,3080 5310,3080 5380,3080 5450,3080 4320,3750 4390,3750 4460,3750 4550,3750 4620,3750 4690,3750 4780,3750 4850,3750 4920,3750 5010,3750 5080,3750 5150,3750 5260,3750 5330,3750 5400,3750 5470,3750 5540,3750 5610,3750 5680,3750 5750,3750 5820,3750 5890,3750 5960,3750 6030,3750 6100,3750 4710,4000 4780,4000 4780,4070 4780,4140 4780,4210 4710,4280 4780,4280 5690,4360 5760,4360 5900,4360 5970,4360 5760,4440 5830,4440 5900,4440 4260,4540 4400,4540 4610,4540 4750,4540 4960,4540 5100,4540 5310,4540 5450,4540 4260,4590 4330,4590 4400,4590 4610,4590 4680,4590 4750,4590 4960,4590 5030,4590 5100,4590 5310,4590 5380,4590 5450,4590 4320,5260 4390,5260 4460,5260 4550,5260 4620,5260 4690,5260 4780,5260 4850,5260 4920,5260 5010,5260 5080,5260 5150,5260 5260,5260 5330,5260 5400,5260 5470,5260 5540,5260 5610,5260 5680,5260 5750,5260 5820,5260 5890,5260 5960,5260 6030,5260 6100,5260 4710,5510 4780,5510 4780,5580 4780,5650 4780,5720 4710,5790 4780,5790 5690,5870 5760,5870 5900,5870 5970,5870 5760,5950 5830,5950 5900,5950 4260,6050 4400,6050 4610,6050 4750,6050 4960,6050 5100,6050 5310,6050 5450,6050 4260,6100 4330,6100 4400,6100 4610,6100 4680,6100 4750,6100 4960,6100 5030,6100 5100,6100 5310,6100 5380,6100 5450,6100 4320,6770 4390,6770 4460,6770 4550,6770 4620,6770 4690,6770 4780,6770 4850,6770 4920,6770 5010,6770 5080,6770 5150,6770 5260,6770 5330,6770 5400,6770 5470,6770 5540,6770 5610,6770 5680,6770 5750,6770 5820,6770 5890,6770 5960,6770 6030,6770 6100,6770 4710,7020 4780,7020 4780,7090 4780,7160 4780,7230 4710,7300 4780,7300 5690,7380 5760,7380 5900,7380 5970,7380 5760,7460 5830,7460 5900,7460 4260,7560 4400,7560 4610,7560 4750,7560 4960,7560 5100,7560 5310,7560 5450,7560 4260,7610 4330,7610 4400,7610 4610,7610 4680,7610 4750,7610 4960,7610 5030,7610 5100,7610 5310,7610 5380,7610 5450,7610
CS2A_A: L300_PS4.1 R300_PS4.1 R915_LM2.2 | length 3680.8
  Top Layer w10: R300_PS4.1@4376.61,7160 v1(4510,7160) ; R915_LM2.2@7521.5,6270 v1(7570,6270)
  Signal Layer 1 w10: v1(4510,7160) 4530,7140 4530,7020 4590,6960 6590,6960 7240,6310 7530,6310 v1(7570,6270)
  other v1: 3840,7070 4300,7090 4250,7120 3840,7140 4300,7160 4250,7200 3840,7210 4300,7230 3840,7280 3840,7350 3840,7420 3840,7480 3910,7480 3980,7480 3840,7760 3910,7760 3980,7760
CS2A_B: L300_PS2.1 R300_PS2.1 R915_LM1.2 | length 3698.4
  Top Layer w10: R300_PS2.1@4376.61,4140 v1(4510,4140) ; R915_LM1.2@7521.5,3250 v1(7570,3250)
  Signal Layer 1 w10: v1(4510,4140) 4530,4120 4530,4000 4590,3940 6520,3940 6910,3550 6910,3520 7040,3390 7150,3390 7250,3290 7530,3290 v1(7570,3250)
  other v1: 3840,4050 4300,4070 4250,4100 3840,4120 4300,4140 4250,4180 3840,4190 4300,4210 3840,4260 3840,4330 3840,4400 3840,4460 3910,4460 3980,4460 3840,4740 3910,4740 3980,4740
DIR: R809.1 U800.1 U801.40 U900_LM1.44 U900_LM2.44 | length 5207
  Top Layer w10: v1(6770,5370) 6720,5320 6720,4930 6860,4790 6860,4600 6941.5,4518.5 R809.1@6941.5,4480 6980,4480 6990,4470 6990,4450 7000.79,4439.21 U801.40@7033.66,4439.21 7070,4439.21 7089.21,4420 7250,4420 7310,4360 7310,4280 7330,4260 7400,4260 7430,4230 7430,4170 7460,4140 7460,3770 7455.59,3765.59 ; U900_LM1.44@7376.34,2969.53 7429.53,2969.53 7460,3000 7640,3000 7660,3020 7660,3130 7620,3170 7620,3390 7500,3510 7470,3510 7440,3540 7440,3750 7455.59,3765.59 ; U900_LM2.44@7376.34,5989.53 7429.53,5989.53 7470,6030 7660,6030 7700,5990 v1(7700,5510) ; U800.1@7515.71,3765.59 7455.59,3765.59
  Signal Layer 1 w10: v1(6770,5370) 6800,5400 7430,5400 7460,5370 7560,5370 v1(7700,5510)
EMU0: J800.13 R800.2 | length 70.3
  Top Layer w10: R800.2@6830,5201.5 6899.18,5201.5 J800.13@6900,5202.31
EMU1: J800.14 R803.2 | length 70.4
  Top Layer w10: R803.2@6830,5008.5 6898.93,5008.5 J800.14@6900,5007.43
EN1_A: R916_LM2.1 U801.28 U900_LM2.39 | length 1909.3
  Top Layer w10: U801.28@7249.21,4556.34 7249.21,4779.21 7340,4870 7520,4870 7610,4960 7610,5230 7521.5,5318.5 R916_LM2.1@7521.5,5550 7590,5550 7620,5580 7620,5820 7590,5850 7470,5850 7428.9,5891.1 U900_LM2.39@7376.34,5891.1
EN1_B: R916_LM1.1 U801.38 U900_LM1.39 | length 3084.2
  Top Layer w10: U801.38@7033.66,4478.58 7068.58,4478.58 v1(7090,4500) ; U900_LM1.39@7376.34,2871.1 7428.9,2871.1 7470,2830 7590,2830 7600,2820 v1(7650,2820) 7650,2800 7620,2770 7620,2570 7580,2530 R916_LM1.1@7521.5,2530
  Signal Layer 1 w10: v1(7090,4500) 7090,4530 7120,4560 7530,4560 v1(7590,4500)
  Signal Layer 2 w10: v1(7590,4500) 7560,4470 7560,3790 7680,3670 7680,3040 7620,2980 7620,2850 v1(7650,2820)
EN2_A: R917_LM2.1 U801.37 U900_LM2.43 | length 3827
  Top Layer w10: U801.37@7033.66,4498.27 6991.73,4498.27 6880,4610 6880,4800 6740,4940 6740,5300 6840,5400 v1(7490,5400) ; U900_LM2.43@7376.34,5969.84 7439.84,5969.84 7480,6010 7650,6010 7680,5980 7680,5640 7670,5630 v1(7670,5580) ; R917_LM2.1@7458.5,6450 7460,6451.5 v1(7460,6490)
  Signal Layer 2 w10: v1(7460,6490) 7510,6440 7510,5790 7540,5760 7640,5760 7670,5730 v1(7670,5580) v1(7490,5400)
EN2_B: R917_LM1.1 U801.39 U900_LM1.43 | length 2407.4
  Top Layer w10: U801.39@7033.66,4458.9 v1(7118.9,4458.9) ; v1(7360,3490) 7360,3420 7380,3400 7428.5,3400 R917_LM1.1@7458.5,3430 ; U900_LM1.43@7376.34,2949.84 7439.84,2949.84 7471.57,2981.57 7651.57,2981.57 7680,3010 7680,3140 7640,3180 7640,3400 7600,3440 7600,3460 v1(7570,3490)
  Signal Layer 1 w10: v1(7360,3490) v1(7570,3490)
  Signal Layer 2 w10: v1(7118.9,4458.9) 7140,4437.8 7140,3710 v1(7360,3490)
EN12: J702.5 R402.1 | length 6114.7
  Top Layer w10: v1(4900,1040) R402.1@4938.5,1040
  Signal Layer 1 w10: v1(4900,1040) 5220,720 6700,720 6760,780 6760,1160 7020,1420 7020,1570 7080,1630 v1(7650,1630)
  Signal Layer 2 w10: v1(7650,1630) 7650,2340 7680,2370 7750,2370 7790,2410 7790,3670 7750,3710 7750,3950 J702.5@7800,4000
EN48: J702.6 U100.5 | length 6502.9
  Top Layer w8: U100.5@3620,1659.37 v1(3620,1710)
  Signal Layer 1 w10: v1(3620,1710) 3740,1710 3760,1690 3870,1690 3970,1790 7550,1790 v1(7580,1760)
  Signal Layer 2 w10: v1(7580,1760) 7630,1810 7630,2350 7670,2390 7740,2390 7770,2420 7770,3660 7650,3780 7650,3950 J702.6@7700,4000
GND: C103.2 C104.2 C105.2 C106.2 C107.2 C108.2 C200.2 C201.2 C202.2 C203.2 C204.2 C300_PS1.2 C300_PS2.2 C300_PS3.2 C300_PS4.2 C301_PS1.2 C301_PS2.2 C301_PS3.2 C301_PS4.2 C302_PS1.2 C302_PS2.2 C302_PS3.2 C302_PS4.2 C303_PS1.2 C303_PS2.2 C303_PS3.2 C303_PS4.2 C304_PS1.2 C304_PS2.2 C304_PS3.2 C304_PS4.2 C305_PS1.2 C305_PS2.2 C305_PS3.2 C305_PS4.2 C306_PS1.2 C306_PS2.2 C306_PS3.2 C306_PS4.2 C307_PS1.2 C307_PS2.2 C307_PS3.2 C307_PS4.2 C308_PS1.2 C308_PS2.2 C308_PS3.2 C308_PS4.2 C309_PS1.2 C309_PS2.2 C309_PS3.2 C309_PS4.2 C310_PS1.2 C310_PS2.2 C310_PS3.2 C310_PS4.2 C311_PS1.2 C311_PS2.2 C311_PS3.2 C311_PS4.2 C312_PS1.2 C312_PS2.2 C312_PS3.2 C312_PS4.2 C313_PS1.2 C313_PS2.2 C313_PS3.2 C313_PS4.2 C314_PS1.2 C314_PS2.2 C314_PS3.2 C314_PS4.2 C315_PS1.2 C315_PS2.2 C315_PS3.2 C315_PS4.2 C316_PS1.2 C316_PS2.2 C316_PS3.2 C316_PS4.2 C317_PS1.2 C317_PS2.2 C317_PS3.2 C317_PS4.2 C318_PS1.2 C318_PS2.2 C318_PS3.2 C318_PS4.2 C319_PS1.2 C319_PS2.2 C319_PS3.2 C319_PS4.2 C402.2 C403.2 C500.2 C501.2 C502.2 C503.2 C504.2 C506.2 C507.2 C509.2 C510.2 C511.2 C512.2 C515.2 C516.1 C517.2 C518.2 C519.2 C520.2 C600.2 C601.2 C602.2 C603.2 C604.2 C800.2 C801.2 C802.2 C803.1 C804.1 C805.1 C807.2 C808.2 C810.2 C811.2 C812.2 C900_LM1.1 C900_LM2.1 C902_LM1.2 C902_LM2.2 C904_LM1.1 C904_LM2.1 C905_LM1.2 C905_LM2.2 C906_LM1.2 C906_LM2.2 C907_LM1.2 C907_LM2.2 C909_LM1.2 C909_LM2.2 C910_LM1.2 C910_LM2.2 C912_LM1.2 C912_LM2.2 C913_LM1.2 C913_LM2.2 C914_LM1.2 C914_LM2.2 C916_LM1.1 C916_LM2.1 C918_LM1.2 C918_LM2.2 C919_LM1.2 C919_LM2.2 C920_LM1.2 C920_LM2.2 D101.1 D103.2 D104.2 D105.1 D403.1 D604.2 D700.1 D701.1 D902_LM1.1 D902_LM2.1 D903_LM1.1 D903_LM2.1 J3.1 J4.1 J700.2 J700.4 J700.6 J700.8 J700.10 J700.12 J700.14 J700.16 J701.3 J701.4 J701.9 J701.10 J701.15 J701.16 J702.3 J702.4 J702.9 J702.15 J702.16 J800.4 J800.8 J800.10 J800.12 Q302_PS1.3 Q302_PS2.3 Q302_PS3.3 Q302_PS4.3 Q303_PS1.3 Q303_PS2.3 Q303_PS3.3 Q303_PS4.3 Q401.2 R106.2 R107.1 R108.1 R110.1 R308_PS1.1 R308_PS2.1 R308_PS3.1 R308_PS4.1 R309_PS1.1 R309_PS2.1 R309_PS3.1 R309_PS4.1 R403.1 R406.1 R504.1 R509.2 R512.2 R604.1 R801.2 R804.1 R805.1 R822.2 R832.2 R835.1 R836.1 R900_LM1.2 R900_LM2.2 R906_LM1.1 R906_LM2.1 R908_LM1.1 R908_LM2.1 R909_LM1.1 R909_LM2.1 R911_LM1.1 R911_LM2.1 R912_LM1.1 R912_LM2.1 R918_LM1.1 R918_LM2.1 R919_LM1.1 R919_LM2.1 R920_LM1.1 R920_LM2.1 RV400.1 U100.6 U500.2 U500.4 U501.1 U501.5 U501.6 U501.7 U501.8 U501.14 U501.15 U502.2 U502.8 U503.5 U503.7@7160,1480 U600.2 U600.4 U601.4 U602.2 U603.2 U604.3 U605.2 U800.2 U801.12 U801.33 U801.34 U801.44 U801.45 U802.3 U803.4 U804.2 U900_LM1.18 U900_LM1.46 U900_LM1.49 U900_LM2.18 U900_LM2.46 U900_LM2.49 | length 41013.6
  Top Layer w10: U100.6@3449.29,1659.37 3489.37,1659.37 3498.5,1668.5 C108.2@3498.5,1720 ; C603.2@3668.5,3160 3668.5,3191.5 3630,3230 3630,3260 3660,3290 3700,3290 3710,3280 U605.2@3710,3259.53 ; C602.2@3668.5,4668.5 C602.2@3668.5,4670 3668.5,4701.5 3630,4740 3630,4780 3650,4800 3700,4800 3710,4790 U603.2@3710,4769.53 ; C601.2@3668.5,6180 3668.5,6238.5 3680,6250 3700,6250 3710,6260 U602.2@3710,6279.53 ; C600.2@3668.5,7690 3690.31,7711.81 3690.31,7730.47 3690.31,7755.31 3710,7775 U600.2@3710,7789.53 ; C504.2@6828.5,560 6828.5,531.5 v1(6850,510) ; C509.2@6828.5,680 6828.5,708.5 v1(6850,730) ; v1(6930,2990) 6970.16,2949.84 U900_LM1.18@7043.66,2949.84 U900_LM1.49@7200.16,2949.84 ; v1(6930,6010) 6970.16,5969.84 U900_LM2.18@7043.66,5969.84 U900_LM2.49@7200.16,5969.84 ; v1@6980,1920 v1(6980,1918.35) D604.2@7010,1918.35 ; U501.14@6986.81,523.23 7046.77,523.23 ; U501.8@6986.81,676.77 7053.23,676.77 ; U502.2@7008.46,1112.8 7062.6,1112.8 ; U803.4@7011.22,3655 v1(7060,3655) ; R512.2@7021.3,1200 R512.2@7021.5,1200 7069.8,1200 ; C802.2@7078.5,4760 7081.5,4760 C805.1@7141.5,4700 C804.1@7141.5,4640 ; U604.3@7122.76,1790 7122.76,1812.76 7152.72,1842.72 U601.4@7152.72,1885 v1(7200,1885) ; U501.15@7125.59,625.59 U501.5@7213.19,625.59 ; v1@7141.42,1138.39 U502.8@7191.34,1138.39 ; 7146.77,676.77 U501.7@7213.19,676.77 ; U501.15@7151.18,651.18 U501.6@7213.19,651.18 ; 7153.23,523.23 U501.1@7213.19,523.23 ; U503.5@7160,1441.61 U503.7@7160,1480 ; C807.2@7174.88,3860 C807.2@7180,3854.88 ; v2(7210,2940) v2(7249.37,2979.37) 7278.9,3008.9 U900_LM1.46@7376.34,3008.9 ; v2(7210,5960) v2(7249.37,5999.37) 7278.9,6028.9 U900_LM2.46@7376.34,6028.9 ; U801.12@7308.27,4223.66 7311.93,4220 v1(7360,4220) ; U802.3@7377.24,3940 7410,3940 7440,3970 7440,4101.5 C803.1@7381.5,4160 ; U804.2@7515.71,3570 7540,3570 7550,3580 7550,3618.5 C811.2@7528.5,3640 ; U800.2@7515.71,3740 7540,3740 7550,3750 7550,3788.5 C812.2@7528.5,3810
  Top Layer w20: R106.2@2960,1591.5 2960,1620 2970,1630 C106.2@2970,1680 ; C107.2@3387.24,1412.76 D105.1@3442.6,1412.76 v1(3442.6,1460) 3540,1460 3562.6,1437.4 D101.1@3562.6,1412.76 ; 4700,1300 4710,1310 4710,1320 4725,1335 U500.2@4752.72,1335
  Top Layer w30: R309_PS1.1@2520,2541.5 Q303_PS1.3@2572.44,2541.5 ; R309_PS2.1@2520,4051.5 Q303_PS2.3@2572.44,4051.5 ; R309_PS3.1@2520,5561.5 Q303_PS3.3@2572.44,5561.5 ; R309_PS4.1@2520,7071.5 Q303_PS4.3@2572.44,7071.5 ; R308_PS1.1@2960,2541.5 Q302_PS1.3@3012.44,2541.5 ; R308_PS2.1@2960,4051.5 Q302_PS2.3@3012.44,4051.5 ; R308_PS3.1@2960,5561.5 Q302_PS3.3@3012.44,5561.5 ; R308_PS4.1@2960,7071.5 Q302_PS4.3@3012.44,7071.5 ; C106.2@2970,1680 v1(2970,1720) ; R110.1@3180,1698.5 v1(3210,1698.5) ; v1(3470.02,1720) C108.2@3498.5,1720 ; v1(3668.5,3130) C603.2@3668.5,3160 ; v1(3668.5,4640) C602.2@3668.5,4668.5 ; v1(3668.5,6150) C601.2@3668.5,6180 ; v1(3668.5,7660) C600.2@3668.5,7690 ; R107.1@3751.5,1550 v1(3779.98,1550) ; R108.1@3751.5,1730 v1(3779.98,1730) ; R504.1@5101.5,1240 v1(5130,1240) ; R406.1@6688.5,1840 v1(6688.5,1870) ; v1(6730,5540) 6758.5,5540 R919_LM2.1@6760,5538.5 C919_LM2.2@6820,5538.5 R900_LM2.2@6880,5538.5 v1(6880,5510) ; v1(6740,3870) R835.1@6740,3898.5 ; R919_LM1.1@6758.5,2520 R919_LM1.1@6760,2518.5 ; v1(6760,2490) R919_LM1.1@6760,2518.5 ; v1(6760,2890) 6780,2890 C910_LM1.2@6820,2930 ; C913_LM1.2@6780,3311.5 v1(6780,3340) ; v1(6780,5880) 6780,5910 C910_LM2.2@6820,5950 ; C913_LM2.2@6780,6331.5 v1(6780,6360) ; v1(6800,3870) R836.1@6800,3898.5 ; R920_LM1.1@6840,3311.5 v1(6840,3340) ; R920_LM2.1@6840,6331.5 v1(6840,6360) ; v1(6880,2490) R900_LM1.2@6880,2518.5 C919_LM1.2@6820,2518.5 R919_LM1.1@6760,2518.5 ; C801.2@6951.5,4340 6962.13,4350.63 v1(7080,4350.63) ; C920_LM1.2@6960,3311.5 6960,3340 v1(6980,3360) ; C920_LM2.2@6960,6331.5 v1(6960,6360) ; v1(6990,3528.5) v1(7250,3528.5) ; C900_LM1.1@7000,2518.5 C906_LM1.2@7060,2518.5 v1(7060,2490) ; J800.12@7000,5007.43 v1(7000,5090) ; C900_LM2.1@7000,5538.5 C906_LM2.2@7060,5538.5 v1(7060,5510) ; R918_LM1.1@7020,3311.5 v1(7020,3340) ; R918_LM2.1@7020,6331.5 v1(7020,6360) ; R604.1@7070,2091.5 v1(7070,2120) ; C918_LM1.2@7080,3311.5 v1(7080,3340) ; C918_LM2.2@7080,6331.5 v1(7080,6360) ; J800.10@7100,5007.43 v1(7100,5090) ; C905_LM1.2@7140,3311.5 v1(7140,3340) ; C905_LM2.2@7140,6331.5 v1(7140,6360) ; v1(7140.94,4520) 7140.94,4639.45 C804.1@7141.5,4640 ; C807.2@7178.5,3860 7180,3858.5 7180,3854.88 v1(7180,3830) ; v1(7180,2490) R912_LM1.1@7180,2518.5 ; v1(7180,5510) R912_LM2.1@7180,5538.5 ; J800.8@7200,5007.43 v1(7200,5090) ; v1(7240,2490) C909_LM1.2@7240,2518.5 ; v1(7240,5510) C909_LM2.2@7240,5538.5 ; C907_LM1.2@7270,3376.93 v1(7270,3410) ; C907_LM2.2@7270,6396.93 v1(7270,6430) ; C604.2@7288.5,2090 v1(7288.5,2120) ; v1(7360,4220) 7381.5,4198.5 C803.1@7381.5,4160 ; v1(7370,3368.5) D903_LM1.1@7400,3368.5 ; v1(7370,6388.5) D903_LM2.1@7400,6388.5 ; v1(7400,2500) D902_LM1.1@7400,2528.5 ; J800.4@7400,5007.43 v1(7400,5090) ; v1(7400,5520) D902_LM2.1@7400,5548.5 ; v1(7500,3640) C811.2@7528.5,3640 ; v1(7500,3810) C812.2@7528.5,3810 ; C904_LM1.1@7521.5,2590 v1(7550,2590) ; C902_LM1.2@7521.5,2770 v1(7550,2770) ; C916_LM1.1@7521.5,3190 v1(7550,3190) ; C914_LM1.2@7521.5,3370 v1(7550,3370) ; C904_LM2.1@7521.5,5610 v1(7550,5610) ; C902_LM2.2@7521.5,5790 v1(7550,5790) ; C916_LM2.1@7521.5,6210 v1(7550,6210) ; C914_LM2.2@7521.5,6390 v1(7550,6390) ; R909_LM1.1@7561.5,3110 C912_LM1.2@7561.5,3050 7562.99,3048.5 R906_LM1.1@7620,3048.5 v1(7620,3030) ; R909_LM2.1@7561.5,6130 C912_LM2.2@7561.5,6070 7562.99,6068.5 R906_LM2.1@7620,6068.5 7621.5,6070 v1(7650,6070) ; R805.1@7570,5151.5 v1(7570,5180) ; D701.1@7591.5,3870 v1(7620,3870) ; D700.1@7591.5,3920 v1(7620,3920) ; R804.1@7591.5,4400 v1(7620,4400) ; C800.2@7591.5,4460 v1(7620,4460) ; R908_LM1.1@7621.5,2890 v1(7650,2890) ; R911_LM1.1@7621.5,2950 v1(7650,2950) ; R908_LM2.1@7621.5,5910 v1(7650,5910) ; R911_LM2.1@7621.5,5970 v1(7650,5970) ; v1(7710,3530) R801.2@7738.5,3530
  Signal Layer 1 w10: v1(3668.5,3130) 3718.5,3180 3980,3180 4040,3240 6280,3240 6710.55,2809.45 6710.55,2780 6730.55,2760 v1(6760,2760) ; v1(3668.5,4640) 3718.5,4690 3980,4690 4040,4750 6680,4750 v1(6720,4710) ; v1(3668.5,6150) 3718.5,6200 3980,6200 4040,6260 6280,6260 6660,5880 6720,5880 6730,5890 6750,5890 6760,5880 v1(6780,5880) ; v1(3668.5,7660) 3718.5,7710 3980,7710 4040,7770 6600,7770 6690,7680 v1(6750,7680)
  Signal Layer 1 w30: v1(2640,2600) v1(2700,2600) v1(2760,2600) 2820,2600 3070,2350 4050,2350 4120,2420 4120,2880 4180,2940 5410,2940 5590,2760 6580,2760 6700,2640 6820,2640 7050,2870 7070,2870 7100.63,2900.63 v2(7131.26,2900.63) ; v1(2640,4110) v1(2700,4110) v1(2760,4110) 2820,4110 3130,3800 6120,3800 v1(6930,2990) ; v1(2640,5620) v1(2700,5620) v1(2760,5620) 2820,5620 3070,5370 4050,5370 4120,5440 4120,5900 4180,5960 5410,5960 5590,5780 6860,5780 6970,5890 7070,5890 7100.63,5920.63 v2(7131.26,5920.63) ; v1(2640,7130) v1(2700,7130) v1(2760,7130) 2820,7130 3130,6820 6120,6820 v1(6930,6010)
  Bottom Layer w30: 6620,1870 v1(6688.5,1870)
  other v1: 200,300 270,300 410,300 480,300 750,300 820,300 960,300 1030,300 1300,300 1370,300 1510,300 1580,300 1850,300 1920,300 2060,300 2130,300 2400,300 2470,300 2610,300 2680,300 270,370 340,370 410,370 820,370 890,370 960,370 1370,370 1440,370 1510,370 1920,370 1990,370 2060,370 2470,370 2540,370 2610,370 7070,1060 7100,1060 7130,1060 7070,1100 7100,1100 7130,1100 7070,1140 7100,1140 7130,1140 4170,1280 4240,1280 4380,1280 4450,1280 4240,1350 4310,1350 4380,1350 7070,1410 7070,1480 7070,1550 630,2130 770,2130 990,2130 1130,2130 1340,2130 1480,2130 630,2180 700,2180 770,2180 990,2180 1060,2180 1130,2180 1340,2180 1410,2180 1480,2180 1640,2180 1710,2180 1780,2180 1870,2180 1940,2180 2010,2180 2100,2180 2170,2180 2240,2180 2330,2180 2400,2180 2470,2180 4320,2180 4390,2180 4460,2180 4550,2180 4620,2180 4690,2180 4780,2180 4850,2180 4920,2180 5010,2180 5080,2180 5150,2180 3250,2440 3320,2440 3390,2440 3460,2440 3530,2440 3600,2440 3670,2440 3740,2440 3810,2440 3880,2440 3950,2440 4020,2440 2640,2480 2700,2480 2760,2480 3080,2480 3140,2480 3200,2480 2640,2540 2700,2540 2760,2540 3080,2540 3140,2540 3080,2600 5760,2990 5830,2990 5900,2990 3210,3040 5690,3060 5760,3060 5900,3060 5970,3060 3210,3080 640,3140 710,3140 780,3140 990,3140 1060,3140 1130,3140 1340,3140 1410,3140 1480,3140 4260,3140 4330,3140 4400,3140 4610,3140 4680,3140 4750,3140 4960,3140 5030,3140 5100,3140 5310,3140 5380,3140 5450,3140 640,3190 780,3190 990,3190 1130,3190 1340,3190 1480,3190 4260,3190 4400,3190 4610,3190 4750,3190 4960,3190 5100,3190 5310,3190 5450,3190 630,3640 770,3640 990,3640 1130,3640 1340,3640 1480,3640 630,3690 700,3690 770,3690 990,3690 1060,3690 1130,3690 1340,3690 1410,3690 1480,3690 1640,3690 1710,3690 1780,3690 1870,3690 1940,3690 2010,3690 2100,3690 2170,3690 2240,3690 2330,3690 2400,3690 2470,3690 4320,3690 4390,3690 4460,3690 4550,3690 4620,3690 4690,3690 4780,3690 4850,3690 4920,3690 5010,3690 5080,3690 5150,3690 3250,3950 3320,3950 3390,3950 3460,3950 3530,3950 3600,3950 3670,3950 3740,3950 3810,3950 3880,3950 3950,3950 4020,3950 4090,3950 2640,3990 2700,3990 2760,3990 3080,3990 3140,3990 3200,3990 2640,4050 2700,4050 2760,4050 3080,4050 3140,4050 3080,4110 5760,4500 5830,4500 5900,4500 3210,4550 5690,4570 5760,4570 5900,4570 5970,4570 3210,4590 640,4650 710,4650 780,4650 990,4650 1060,4650 1130,4650 1340,4650 1410,4650 1480,4650 4260,4650 4330,4650 4400,4650 4610,4650 4680,4650 4750,4650 4960,4650 5030,4650 5100,4650 5310,4650 5380,4650 5450,4650 640,4700 780,4700 990,4700 1130,4700 1340,4700 1480,4700 4260,4700 4400,4700 4610,4700 4750,4700 4960,4700 5100,4700 5310,4700 5450,4700 630,5150 770,5150 990,5150 1130,5150 1340,5150 1480,5150 630,5200 700,5200 770,5200 990,5200 1060,5200 1130,5200 1340,5200 1410,5200 1480,5200 1640,5200 1710,5200 1780,5200 1870,5200 1940,5200 2010,5200 2100,5200 2170,5200 2240,5200 2330,5200 2400,5200 2470,5200 4320,5200 4390,5200 4460,5200 4550,5200 4620,5200 4690,5200 4780,5200 4850,5200 4920,5200 5010,5200 5080,5200 5150,5200 3250,5460 3320,5460 3390,5460 3460,5460 3530,5460 3600,5460 3670,5460 3740,5460 3810,5460 3880,5460 3950,5460 4020,5460 2640,5500 2700,5500 2760,5500 3080,5500 3140,5500 3200,5500 2640,5560 2700,5560 2760,5560 3080,5560 3140,5560 3080,5620 5760,6010 5830,6010 5900,6010 3210,6060 5690,6080 5760,6080 5900,6080 5970,6080 3210,6100 640,6160 710,6160 780,6160 990,6160 1060,6160 1130,6160 1340,6160 1410,6160 1480,6160 4260,6160 4330,6160 4400,6160 4610,6160 4680,6160 4750,6160 4960,6160 5030,6160 5100,6160 5310,6160 5380,6160 5450,6160 640,6210 780,6210 990,6210 1130,6210 1340,6210 1480,6210 4260,6210 4400,6210 4610,6210 4750,6210 4960,6210 5100,6210 5310,6210 5450,6210 630,6660 770,6660 990,6660 1130,6660 1340,6660 1480,6660 630,6710 700,6710 770,6710 990,6710 1060,6710 1130,6710 1340,6710 1410,6710 1480,6710 1640,6710 1710,6710 1780,6710 1870,6710 1940,6710 2010,6710 2100,6710 2170,6710 2240,6710 2330,6710 2400,6710 2470,6710 4320,6710 4390,6710 4460,6710 4550,6710 4620,6710 4690,6710 4780,6710 4850,6710 4920,6710 5010,6710 5080,6710 5150,6710 3250,6970 3320,6970 3390,6970 3460,6970 3530,6970 3600,6970 3670,6970 3740,6970 3810,6970 3880,6970 3950,6970 4020,6970 4090,6970 2640,7010 2700,7010 2760,7010 3080,7010 3140,7010 3200,7010 2640,7070 2700,7070 2760,7070 3080,7070 3140,7070 3080,7130 5760,7520 5830,7520 5900,7520 3210,7570 5690,7590 5760,7590 5900,7590 5970,7590 3210,7610 640,7670 710,7670 780,7670 990,7670 1060,7670 1130,7670 1340,7670 1410,7670 1480,7670 4260,7670 4330,7670 4400,7670 4610,7670 4680,7670 4750,7670 4960,7670 5030,7670 5100,7670 5310,7670 5380,7670 5450,7670 640,7720 780,7720 990,7720 1130,7720 1340,7720 1480,7720 4260,7720 4400,7720 4610,7720 4750,7720 4960,7720 5100,7720 5310,7720 5450,7720
  other v2: 7138.35,1480 7181.65,1480 7131.26,2861.26 7170.63,2861.26 7210,2861.26 7249.37,2861.26 7288.74,2861.26 7170.63,2900.63 7210,2900.63 7249.37,2900.63 7288.74,2900.63 7131.26,2940 7170.63,2940 7249.37,2940 7288.74,2940 7131.26,2979.37 7170.63,2979.37 7210,2979.37 7288.74,2979.37 7131.26,3018.74 7170.63,3018.74 7210,3018.74 7249.37,3018.74 7288.74,3018.74 7131.26,5881.26 7170.63,5881.26 7210,5881.26 7249.37,5881.26 7288.74,5881.26 7170.63,5920.63 7210,5920.63 7249.37,5920.63 7288.74,5920.63 7131.26,5960 7170.63,5960 7249.37,5960 7288.74,5960 7131.26,5999.37 7170.63,5999.37 7210,5999.37 7288.74,5999.37 7131.26,6038.74 7170.63,6038.74 7210,6038.74 7249.37,6038.74 7288.74,6038.74
  other v3: 7060.63,560.63 7100,560.63 7139.37,560.63 7060.63,600 7100,600 7139.37,600 7060.63,639.37 7100,639.37 7139.37,639.37
HO1_A: R302_PS3.1 R305_PS3.1 U900_LM2.22 | length 6386.9
  Top Layer w10: U900_LM2.22@7043.66,5891.1 7078.9,5891.1 7090,5880 7090,5840 v1(7070,5820)
  Top Layer w30: v1(2130,5570) R302_PS3.1@2168.5,5570 ; v1(2130,6010) R305_PS3.1@2168.5,6010
  Signal Layer 1 w30: v1(2130,6010) v1(2130,5570) 2320,5380 2890,5380 3020,5250 4110,5250 4210,5350 4210,5790 4260,5840 5370,5840 5550,5660 6970,5660 7070,5760 v1(7070,5820)
HO1_B: R302_PS1.1 R305_PS1.1 U900_LM1.22 | length 6469.7
  Top Layer w10: U900_LM1.22@7043.66,2871.1 7078.9,2871.1 7090,2860 7090,2820 v1(7070,2800)
  Top Layer w30: v1(2130,2550) R302_PS1.1@2168.5,2550 ; v1(2130,2990) R305_PS1.1@2168.5,2990
  Signal Layer 1 w30: v1(2130,2990) v1(2130,2550) 2320,2360 2890,2360 3020,2230 4110,2230 4210,2330 4210,2770 4260,2820 5370,2820 5550,2640 6540,2640 6640,2540 6870,2540 7070,2740 v1(7070,2800)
